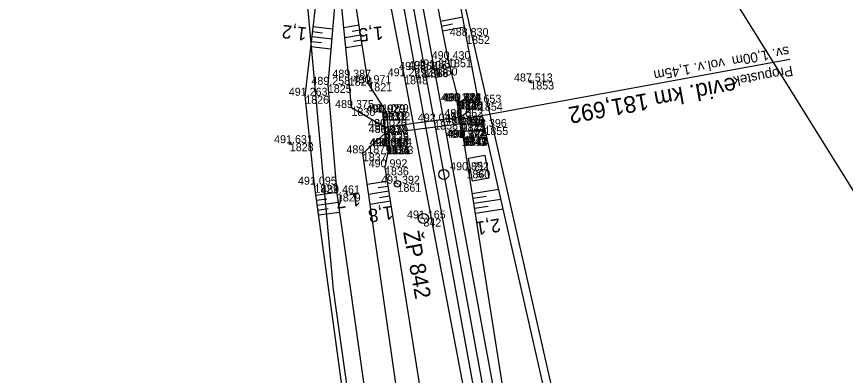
# Model space of a CAD drawing. Extents: x -1234191 to 23050, y -1290331 to -741191.
# Drawn here: x -865141.5 to -865017.2, y -1107455.9 to -1107402.1 of the extents above; entities that cross this region are included whole.
import ezdxf

# ---------------------------------------------------------------- set-up
doc = ezdxf.new("R2010")
doc.units = 0
for name, color, linetype in [('Vrstva 1', 7, 'Continuous'), ('Vrstva 19', 7, 'Continuous'), ('Vrstva 4', 7, 'Continuous'), ('Vrstva 48', 7, 'Continuous'), ('Vrstva 49', 7, 'Continuous'), ('Vrstva 53', 7, 'Continuous'), ('Vrstva 55', 7, 'Continuous'), ('Vrstva 60', 7, 'Continuous'), ('Vrstva 61', 7, 'Continuous'), ('Vrstva 63', 7, 'Continuous'), ('Vrstva 7', 7, 'Continuous')]:
    doc.layers.add(name, color=color, linetype=linetype)

msp = doc.modelspace()

# ---------------------------------------------------------------- linework, layer by layer
at = {"layer": 'Vrstva 1'}
msp.add_lwpolyline([(-865134.6, -1107197.69), (-865124.47, -1107222.35), (-865115.52, -1107247.85), (-865108.44, -1107271.77), (-865102.71, -1107293.86), (-865097.88, -1107316.03), (-865093.53, -1107338.23), (-865089.35, -1107360.68), (-865080.34, -1107409.99), (-865080.33, -1107410.02), (-865078.89, -1107417.87), (-865071.37, -1107459.09), (-865062.43, -1107508.14), (-865053.45, -1107557.3), (-865047.38, -1107590.6), (-865041.22, -1107624.26), (-865037.22, -1107646.41), (-865033.4, -1107668.58), (-865029.98, -1107690.86), (-865027.26, -1107713.25)], dxfattribs=at)
at = {"layer": 'Vrstva 19'}
for p, q in [((-865025.58, -1107408.58), (-865074.77, -1107417.56)), ((-865075.21, -1107414.83), (-865074.9, -1107417.19)), ((-865075.12, -1107414.82), (-865075.12, -1107414.82)), ((-865074.41, -1107420.29), (-865075.12, -1107414.82)), ((-865074.41, -1107420.29), (-865075.12, -1107414.82)), ((-865086.63, -1107416.53), (-865086.15, -1107421.58)), ((-865086.63, -1107416.53), (-865086.63, -1107416.53)), ((-865086.54, -1107416.52), (-865086.05, -1107416.47)), ((-865086.54, -1107416.52), (-865086.33, -1107418.7)), ((-865086.33, -1107418.7), (-865074.9, -1107417.19)), ((-865086.33, -1107418.7), (-865074.9, -1107417.19)), ((-865074.9, -1107417.19), (-865074.9, -1107417.19)), ((-865086.33, -1107418.7), (-865086.33, -1107418.7)), ((-865086.25, -1107419.6), (-865074.77, -1107418.19)), ((-865086.25, -1107419.6), (-865074.77, -1107418.19)), ((-865074.5, -1107420.3), (-865074.77, -1107418.19)), ((-865086.06, -1107421.57), (-865086.25, -1107419.6)), ((-865074.41, -1107420.29), (-865074.41, -1107420.29)), ((-865086.15, -1107421.58), (-865086.15, -1107421.58))]:
    msp.add_line(p, q, dxfattribs=at)
for points in [[(-865074.41, -1107420.29), (-865074.72, -1107420.33), (-865075.43, -1107414.86), (-865075.12, -1107414.82)], [(-865075.21, -1107414.83), (-865075.21, -1107414.83), (-865075.43, -1107414.86)], [(-865074.41, -1107420.29), (-865074.5, -1107420.3), (-865075.21, -1107414.83), (-865075.12, -1107414.82)], [(-865086.63, -1107416.53), (-865086.05, -1107416.47), (-865085.58, -1107421.53), (-865086.15, -1107421.58)], [(-865086.63, -1107416.53), (-865086.54, -1107416.52), (-865086.06, -1107421.57)], [(-865086.63, -1107416.53), (-865086.15, -1107421.58), (-865086.06, -1107421.57)], [(-865074.9, -1107417.19), (-865074.77, -1107418.19), (-865074.77, -1107418.19)], [(-865086.33, -1107418.7), (-865086.25, -1107419.6), (-865086.25, -1107419.6)], [(-865074.5, -1107420.3), (-865074.5, -1107420.3), (-865074.72, -1107420.33)], [(-865086.06, -1107421.57), (-865086.06, -1107421.57), (-865085.58, -1107421.53)]]:
    msp.add_lwpolyline(points, dxfattribs=at)
at = {"layer": 'Vrstva 4'}
for points in [[(-865271.55, -1106933.15), (-865268.35, -1106943.65), (-865262.05, -1106962.08), (-865252.65, -1106984.49), (-865242.91, -1107004.09), (-865232.53, -1107023.13), (-865221.46, -1107041.92), (-865210.16, -1107060.85), (-865189.56, -1107095.17), (-865177.27, -1107115.1), (-865166.12, -1107134.16), (-865154.62, -1107154.22), (-865144.26, -1107174.3), (-865133.39, -1107196.86), (-865123.28, -1107221.78), (-865114.21, -1107247.33), (-865107.13, -1107271.34), (-865101.45, -1107293.47), (-865096.61, -1107315.67), (-865092.2, -1107337.76), (-865087.93, -1107360.53), (-865078.96, -1107409.77)], [(-865076.81, -1107408.53), (-865086.19, -1107360.28), (-865090.85, -1107337.52), (-865095.49, -1107315.59), (-865100.08, -1107293.18), (-865105.98, -1107271.04), (-865113.06, -1107246.92), (-865121.97, -1107221.37), (-865132.25, -1107196.44), (-865143.24, -1107173.51), (-865153.52, -1107153.57), (-865165.02, -1107133.51), (-865176.15, -1107114.27), (-865188.18, -1107094.57), (-865209.17, -1107060.36), (-865220.24, -1107041.2), (-865231.43, -1107022.53), (-865239.74, -1107008.36), (-865244.25, -1106997.87), (-865250.7, -1106983.56), (-865260.16, -1106961.26), (-865267.75, -1106943.47), (-865268.35, -1106943.65)], [(-865028.6, -1107713.49), (-865031.37, -1107691.19), (-865034.73, -1107668.92), (-865038.49, -1107646.71), (-865042.61, -1107624.52), (-865048.56, -1107590.94), (-865054.62, -1107557.49), (-865063.64, -1107508.48), (-865072.71, -1107459.19), (-865081.68, -1107410.15), (-865090.67, -1107361), (-865094.96, -1107338.29), (-865099.26, -1107316.16), (-865104.11, -1107294.07), (-865109.82, -1107272.13), (-865116.79, -1107248.15), (-865125.9, -1107222.77), (-865135.88, -1107198.13)], [(-865137.82, -1107199.21), (-865128.67, -1107224.01), (-865118.59, -1107249.61), (-865111.17, -1107273.09), (-865105.44, -1107294.53), (-865100.88, -1107317.07), (-865097.12, -1107338.8), (-865093.03, -1107361.27), (-865083.39, -1107411.09), (-865074.22, -1107459.51), (-865071.26, -1107475.81), (-865065.54, -1107508.7), (-865056.47, -1107557.39), (-865050.26, -1107591.11), (-865046.72, -1107615.18), (-865044.77, -1107624.94), (-865040.7, -1107646.79), (-865036.93, -1107669.17), (-865033.64, -1107691.45), (-865031.02, -1107713.8)], [(-865024.43, -1107713.22), (-865027.33, -1107690.42), (-865030.71, -1107668.18), (-865034.17, -1107645.72), (-865038.63, -1107623.95), (-865044.5, -1107589.98), (-865050.68, -1107556.67), (-865059.77, -1107507.71), (-865068.46, -1107458.63), (-865074.5, -1107420.3), (-865074.72, -1107420.33), (-865075.43, -1107414.86), (-865075.21, -1107414.83), (-865076.81, -1107408.53)], [(-865078.96, -1107409.77), (-865069.86, -1107458.85), (-865061.01, -1107508.05), (-865052.14, -1107557.07), (-865045.91, -1107590.37), (-865039.86, -1107624.08), (-865035.75, -1107646.28), (-865032.1, -1107668.41), (-865028.57, -1107690.77), (-865026.02, -1107713.12)]]:
    msp.add_lwpolyline(points, dxfattribs=at)
at = {"layer": 'Vrstva 48'}
for p, q in [((-865077.92, -1107402.83), (-865074.62, -1107402.19)), ((-865097.02, -1107403.65), (-865094.12, -1107403.98)), ((-865090.12, -1107403.45), (-865092.44, -1107403.82)), ((-865077.78, -1107403.56), (-865076.13, -1107403.24)), ((-865077.63, -1107404.3), (-865074.35, -1107403.66)), ((-865097.2, -1107405.14), (-865094.25, -1107405.48)), ((-865097.11, -1107404.39), (-865095.65, -1107404.56)), ((-865089.88, -1107404.94), (-865092.29, -1107405.31)), ((-865090, -1107404.2), (-865091.18, -1107404.38)), ((-865097.28, -1107405.88), (-865095.8, -1107406.05)), ((-865089.65, -1107406.42), (-865092.14, -1107406.81)), ((-865089.77, -1107405.68), (-865090.99, -1107405.87)), ((-865097.37, -1107406.63), (-865094.38, -1107406.97)), ((-865085.92, -1107426.85), (-865088.92, -1107427.32)), ((-865096.63, -1107428.91), (-865093.49, -1107428.48)), ((-865085.69, -1107428.33), (-865088.71, -1107428.81)), ((-865085.81, -1107427.59), (-865087.31, -1107427.83)), ((-865073.19, -1107428.64), (-865069.24, -1107428.02)), ((-865096.53, -1107429.65), (-865094.96, -1107429.44)), ((-865096.43, -1107430.4), (-865093.29, -1107429.97)), ((-865085.45, -1107429.81), (-865088.49, -1107430.29)), ((-865085.57, -1107429.07), (-865087.08, -1107429.31)), ((-865073.07, -1107429.38), (-865071.07, -1107429.07)), ((-865072.95, -1107430.12), (-865068.9, -1107429.49)), ((-865096.33, -1107431.14), (-865094.76, -1107430.93)), ((-865072.84, -1107430.86), (-865070.79, -1107430.54)), ((-865072.72, -1107431.6), (-865068.57, -1107430.95)), ((-865096.22, -1107431.88), (-865093.08, -1107431.45))]:
    msp.add_line(p, q, dxfattribs=at)
at = {"layer": 'Vrstva 49'}
for p, q in [((-865064.69, -1107411.73), (-865064.28, -1107412.01)), ((-865064.34, -1107411.66), (-865064.63, -1107412.08)), ((-865100.73, -1107420.97), (-865100.32, -1107421.26)), ((-865100.38, -1107420.91), (-865100.67, -1107421.32))]:
    msp.add_line(p, q, dxfattribs=at)
for points in [[(-865074.9, -1107417.19), (-865072.18, -1107415.05), (-865074.1, -1107405.04), (-865082.58, -1107358.94), (-865086.35, -1107336.26), (-865090.03, -1107314.57), (-865094.51, -1107291.81), (-865099.26, -1107269.75), (-865102.65, -1107257.91), (-865107.51, -1107244.92), (-865114.81, -1107218.28), (-865124.92, -1107193.5), (-865136.04, -1107170.58), (-865146.13, -1107150.31), (-865156.6, -1107130.71), (-865169.48, -1107111.06), (-865184.01, -1107092.63), (-865206.67, -1107057.9), (-865209.3, -1107045.87)], [(-865074.9, -1107417.19), (-865075.21, -1107414.83), (-865076.81, -1107408.53), (-865086.19, -1107360.28), (-865089.16, -1107337.27), (-865093.61, -1107315.19), (-865097.54, -1107292.27), (-865102.18, -1107269.46), (-865105.31, -1107258.75), (-865109.86, -1107245.87), (-865119, -1107220.06), (-865128.74, -1107194.89), (-865139.58, -1107171.15), (-865149.96, -1107152.49), (-865160.83, -1107131.9), (-865172.18, -1107112.31), (-865184.96, -1107093.62), (-865206.67, -1107057.9)], [(-865086.05, -1107416.47), (-865088.76, -1107412.13), (-865096.56, -1107362.35), (-865102.54, -1107338.61)], [(-865072.42, -1107556.44), (-865085.52, -1107508.58), (-865090, -1107477.47), (-865096.84, -1107427.34), (-865098.22, -1107414.01), (-865096.04, -1107395.2)], [(-865086.33, -1107418.7), (-865091.28, -1107415.84), (-865091.7, -1107411.3), (-865093.34, -1107394.69), (-865094.83, -1107412.37)], [(-865094.83, -1107412.37), (-865093.48, -1107428.65), (-865086.19, -1107480.28), (-865082.74, -1107507.62), (-865070.53, -1107555.32), (-865052.7, -1107593.7)], [(-865086.33, -1107418.7), (-865086.54, -1107416.52), (-865086.05, -1107416.47)], [(-865022.79, -1107804.44), (-865016.96, -1107788.62), (-865016.32, -1107763.6), (-865014.21, -1107739.62), (-865018.62, -1107713.17), (-865023.32, -1107690.22), (-865023.02, -1107669.46), (-865030.19, -1107644.87), (-865030.19, -1107623.87), (-865039.76, -1107587.33), (-865045.46, -1107556.09), (-865053.81, -1107508.61), (-865062.31, -1107458.43), (-865071.36, -1107418.69), (-865074.77, -1107418.19)], [(-865022.79, -1107804.44), (-865021.82, -1107788.94), (-865019.1, -1107763.89), (-865018.93, -1107738.04), (-865021.67, -1107713.09), (-865025.13, -1107689.6), (-865028.75, -1107668.21), (-865032.03, -1107644.92), (-865036.31, -1107623.58), (-865044.5, -1107589.98), (-865050.68, -1107556.67), (-865059.77, -1107507.71), (-865068.46, -1107458.63), (-865074.5, -1107420.3), (-865074.77, -1107418.19)], [(-865031.02, -1107713.8), (-865033.64, -1107691.45), (-865036.93, -1107669.17), (-865040.7, -1107646.79), (-865044.77, -1107624.94), (-865052.7, -1107593.7), (-865068.43, -1107553.67), (-865078.88, -1107501.98), (-865081.8, -1107476.97), (-865089.59, -1107422.64), (-865086.25, -1107419.6), (-865086.06, -1107421.57), (-865085.58, -1107421.53)], [(-865044.77, -1107624.94), (-865046.72, -1107615.18), (-865051.45, -1107591.69), (-865063.57, -1107553.62), (-865076.14, -1107499.68), (-865079.46, -1107477.35), (-865080.56, -1107460.57), (-865086.26, -1107424.73), (-865085.58, -1107421.53)]]:
    msp.add_lwpolyline(points, dxfattribs=at)
at = {"layer": 'Vrstva 53'}
for points in [[(-865031.84, -1107728.7), (-865056.26, -1107614.01), (-865082.13, -1107527.34), (-865093.98, -1107443.05), (-865102.44, -1107349.87), (-865111.7, -1107288.18), (-865115.78, -1107279.62), (-865126.55, -1107239.39), (-865152.22, -1107173.12), (-865183.78, -1107119.15), (-865210.51, -1107089.36), (-865241.35, -1107035.57), (-865260.95, -1106990.6), (-865287.43, -1106945.67), (-865298.94, -1106904.64), (-865299.65, -1106898.63), (-865300.82, -1106833.27), (-865292.28, -1106759.44), (-865281, -1106690.92)], [(-865092.53, -1107296.42), (-865093.78, -1107297.05), (-865085.74, -1107331.16), (-865081.78, -1107367.84), (-865071.03, -1107414.61), (-865057, -1107476.66), (-865048.71, -1107534.73), (-865038.9, -1107603.03), (-865032.33, -1107641.03), (-865022.47, -1107702.51), (-865004.69, -1107700.09), (-865003.06, -1107712.55)]]:
    msp.add_lwpolyline(points, dxfattribs=at)
at = {"layer": 'Vrstva 55'}
msp.add_lwpolyline([(-864992.74, -1107499.24), (-865005.93, -1107444.46), (-865036.41, -1107395.49), (-865035.2, -1107356.59), (-865040.73, -1107336.47)], dxfattribs=at)
at = {"layer": 'Vrstva 60'}
for p, q in [((-865074.1, -1107405.04), (-865074.1, -1107405.04)), ((-865076.81, -1107408.53), (-865076.81, -1107408.53)), ((-865081.68, -1107410.15), (-865081.68, -1107410.15)), ((-865080.34, -1107409.99), (-865080.34, -1107409.99)), ((-865080.33, -1107410.02), (-865080.33, -1107410.02)), ((-865078.96, -1107409.77), (-865078.96, -1107409.77)), ((-865091.7, -1107411.3), (-865091.7, -1107411.3)), ((-865083.39, -1107411.09), (-865083.39, -1107411.09)), ((-865094.83, -1107412.37), (-865094.83, -1107412.37)), ((-865088.76, -1107412.13), (-865088.76, -1107412.13)), ((-865064.48, -1107411.87), (-865064.48, -1107411.87)), ((-865098.22, -1107414.01), (-865098.22, -1107414.01)), ((-865075.43, -1107414.86), (-865075.43, -1107414.86)), ((-865075.21, -1107414.83), (-865075.21, -1107414.83)), ((-865075.21, -1107414.83), (-865075.21, -1107414.83)), ((-865075.12, -1107414.82), (-865075.12, -1107414.82)), ((-865075.12, -1107414.82), (-865075.12, -1107414.82)), ((-865072.18, -1107415.05), (-865072.18, -1107415.05)), ((-865091.28, -1107415.84), (-865091.28, -1107415.84)), ((-865086.63, -1107416.53), (-865086.63, -1107416.53)), ((-865086.63, -1107416.53), (-865086.63, -1107416.53)), ((-865086.54, -1107416.52), (-865086.54, -1107416.52)), ((-865086.05, -1107416.47), (-865086.05, -1107416.47)), ((-865074.9, -1107417.19), (-865074.9, -1107417.19)), ((-865074.9, -1107417.19), (-865074.9, -1107417.19)), ((-865086.33, -1107418.7), (-865086.33, -1107418.7)), ((-865086.33, -1107418.7), (-865086.33, -1107418.7)), ((-865078.89, -1107417.87), (-865078.89, -1107417.87)), ((-865074.77, -1107418.19), (-865074.77, -1107418.19)), ((-865074.77, -1107418.19), (-865074.77, -1107418.19)), ((-865071.36, -1107418.69), (-865071.36, -1107418.69)), ((-865086.25, -1107419.6), (-865086.25, -1107419.6)), ((-865086.25, -1107419.6), (-865086.25, -1107419.6)), ((-865100.53, -1107421.12), (-865100.53, -1107421.12)), ((-865074.72, -1107420.33), (-865074.72, -1107420.33)), ((-865074.5, -1107420.3), (-865074.5, -1107420.3)), ((-865074.5, -1107420.3), (-865074.5, -1107420.3)), ((-865074.41, -1107420.29), (-865074.41, -1107420.29)), ((-865074.41, -1107420.29), (-865074.41, -1107420.29)), ((-865086.15, -1107421.58), (-865086.15, -1107421.58)), ((-865086.15, -1107421.58), (-865086.15, -1107421.58)), ((-865086.06, -1107421.57), (-865086.06, -1107421.57)), ((-865086.06, -1107421.57), (-865086.06, -1107421.57)), ((-865085.58, -1107421.53), (-865085.58, -1107421.53)), ((-865089.59, -1107422.64), (-865089.59, -1107422.64)), ((-865086.26, -1107424.73), (-865086.26, -1107424.73)), ((-865074.05, -1107425.18), (-865074.05, -1107425.18)), ((-865096.84, -1107427.34), (-865096.84, -1107427.34)), ((-865084.39, -1107427.2), (-865084.39, -1107427.2)), ((-865093.48, -1107428.65), (-865093.48, -1107428.65)), ((-865080.51, -1107432.41), (-865080.51, -1107432.41))]:
    msp.add_line(p, q, dxfattribs=at)
at = {"layer": 'Vrstva 63'}
msp.add_line((-865080.52, -1107432.36), (-865080.5, -1107432.46), dxfattribs=at)
msp.add_circle((-865080.51, -1107432.41), 0.756, dxfattribs=at)
at = {"layer": 'Vrstva 7'}
for p, q in [((-865074.05, -1107425.18), (-865073.44, -1107425.07)), ((-865084.4, -1107427.15), (-865084.38, -1107427.25))]:
    msp.add_line(p, q, dxfattribs=at)
msp.add_lwpolyline([(-865073.75, -1107423.36), (-865071.31, -1107422.91), (-865070.68, -1107426.34), (-865073.13, -1107426.79)], close=True, dxfattribs=at)
for centre, radius in [((-865077.45, -1107425.8), 0.75), ((-865084.39, -1107427.2), 0.5)]:
    msp.add_circle(centre, radius, dxfattribs=at)

# ---------------------------------------------------------------- texts
at = {"layer": 'Vrstva 19'}
for s, height, p in [('sv. 1,00m  vol.v. 1,45m', 1.5, (-865025.81, -1107406.57)), ('Propustek', 1.5, (-865025.27, -1107409.52)), ('evid. km 181,692', 2.5, (-865033.86, -1107411.18))]:
    msp.add_text(s, height=height, rotation=190.3374, dxfattribs=at).set_placement(p)
at = {"layer": 'Vrstva 48'}
for s, rotation, p in [('1,2', 173.3852, (-865097.89, -1107403.79)), ('1,5', 185.632, (-865086.62, -1107403.58)), ('1,7', 187.7734, (-865090.08, -1107428.48)), ('1,8', 189.0408, (-865085.22, -1107430.48)), ('2,1', 188.9465, (-865069.11, -1107432.38))]:
    msp.add_text(s, height=2, rotation=rotation, dxfattribs=at).set_placement(p)
at = {"layer": 'Vrstva 60'}
for s, p in [('1852', (-865074.1, -1107406.24)), ('1851', (-865076.81, -1107409.73)), ('1849', (-865081.68, -1107411.35)), ('1819', (-865080.34, -1107411.19)), ('1856', (-865080.33, -1107411.23)), ('1850', (-865078.96, -1107410.97)), ('1824', (-865091.7, -1107412.5)), ('1848', (-865083.39, -1107412.29)), ('1825', (-865094.83, -1107413.57)), ('1821', (-865088.76, -1107413.33)), ('1853', (-865064.48, -1107413.07)), ('1826', (-865098.22, -1107415.21)), ('9113', (-865075.43, -1107416.06)), ('9120', (-865075.21, -1107416.03)), ('1846', (-865075.21, -1107416.03)), ('9115', (-865075.12, -1107416.02)), ('1845', (-865075.12, -1107416.02)), ('1854', (-865072.18, -1107416.25)), ('1830', (-865091.28, -1107417.04)), ('9117', (-865086.63, -1107417.73)), ('1831', (-865086.63, -1107417.73)), ('9118', (-865086.54, -1107417.72)), ('1832', (-865086.05, -1107417.67)), ('9122', (-865074.9, -1107418.39)), ('1840', (-865074.9, -1107418.39)), ('9123', (-865086.33, -1107419.9)), ('1838', (-865086.33, -1107419.9)), ('1858', (-865078.89, -1107419.07)), ('9124', (-865074.77, -1107419.39)), ('1841', (-865074.77, -1107419.39)), ('1855', (-865071.36, -1107419.89)), ('9125', (-865086.25, -1107420.8)), ('1839', (-865086.25, -1107420.8)), ('1828', (-865100.53, -1107422.32)), ('1843', (-865074.72, -1107421.53)), ('9119', (-865074.5, -1107421.5)), ('1847', (-865074.5, -1107421.5)), ('9114', (-865074.41, -1107421.49)), ('1842', (-865074.41, -1107421.49)), ('9116', (-865086.15, -1107422.78)), ('1834', (-865086.15, -1107422.78)), ('9121', (-865086.06, -1107422.77)), ('1835', (-865086.06, -1107422.77)), ('1833', (-865085.58, -1107422.73)), ('1837', (-865089.59, -1107423.84)), ('1836', (-865086.26, -1107425.93)), ('1860', (-865074.05, -1107426.38)), ('1827', (-865096.84, -1107428.54)), ('1861', (-865084.39, -1107428.4)), ('1829', (-865093.48, -1107429.85)), ('842', (-865080.51, -1107433.61))]:
    msp.add_text(s, height=1.2, dxfattribs=at).set_placement(p)
at = {"layer": 'Vrstva 61'}
for s, p in [('488.830', (-865076.55, -1107405.04)), ('490.430', (-865079.26, -1107408.53)), ('492.107', (-865082.79, -1107409.99)), ('492.106', (-865082.78, -1107410.02)), ('491.830', (-865081.41, -1107409.77)), ('489.387', (-865094.15, -1107411.3)), ('491.229', (-865085.85, -1107411.09)), ('491.868', (-865084.14, -1107410.15)), ('489.258', (-865097.29, -1107412.37)), ('490.971', (-865091.11, -1107412.13)), ('487.513', (-865066.93, -1107411.87)), ('491.263', (-865100.68, -1107414.01)), ('490.374', (-865077.88, -1107414.86)), ('489.918', (-865077.66, -1107414.83)), ('490.224', (-865077.66, -1107414.83)), ('490.374', (-865077.57, -1107414.82)), ('490.224', (-865077.57, -1107414.82)), ('488.653', (-865074.63, -1107415.05)), ('489.375', (-865093.74, -1107415.84)), ('491.079', (-865089.08, -1107416.53)), ('490.929', (-865089.08, -1107416.53)), ('490.929', (-865088.99, -1107416.52)), ('491.079', (-865088.51, -1107416.47)), ('488.562', (-865077.35, -1107417.19)), ('490.053', (-865077.36, -1107417.19)), ('489.020', (-865088.78, -1107418.7)), ('490.075', (-865088.79, -1107418.7)), ('492.044', (-865081.34, -1107417.87)), ('488.599', (-865077.23, -1107418.19)), ('490.053', (-865077.23, -1107418.19)), ('488.396', (-865073.81, -1107418.69)), ('488.933', (-865088.7, -1107419.6)), ('490.078', (-865088.7, -1107419.6)), ('491.631', (-865102.88, -1107421.12)), ('490.372', (-865077.16, -1107420.33)), ('489.994', (-865076.95, -1107420.3)), ('490.222', (-865076.95, -1107420.3)), ('490.372', (-865076.86, -1107420.29)), ('490.222', (-865076.86, -1107420.29)), ('491.094', (-865088.6, -1107421.58)), ('490.944', (-865088.6, -1107421.58)), ('490.515', (-865088.52, -1107421.57)), ('490.944', (-865088.51, -1107421.57)), ('491.094', (-865088.03, -1107421.53)), ('489.187', (-865092.04, -1107422.64)), ('490.992', (-865088.71, -1107424.73)), ('490.892', (-865076.5, -1107425.18)), ('491.095', (-865099.3, -1107427.34)), ('491.392', (-865086.84, -1107427.2)), ('489.461', (-865095.83, -1107428.65)), ('491.165', (-865082.97, -1107432.41))]:
    msp.add_text(s, height=1.2, dxfattribs=at).set_placement(p)
at = {"layer": 'Vrstva 63'}
msp.add_text('ŽP 842', height=2.4, rotation=280.3374, dxfattribs=at).set_placement((-865083.55, -1107434.43))
at = {"layer": 'Vrstva 7'}
msp.add_text('KM', height=1.247, rotation=280.3374, dxfattribs=at).set_placement((-865073.01, -1107423.96))

doc.saveas('drawing.dxf')
